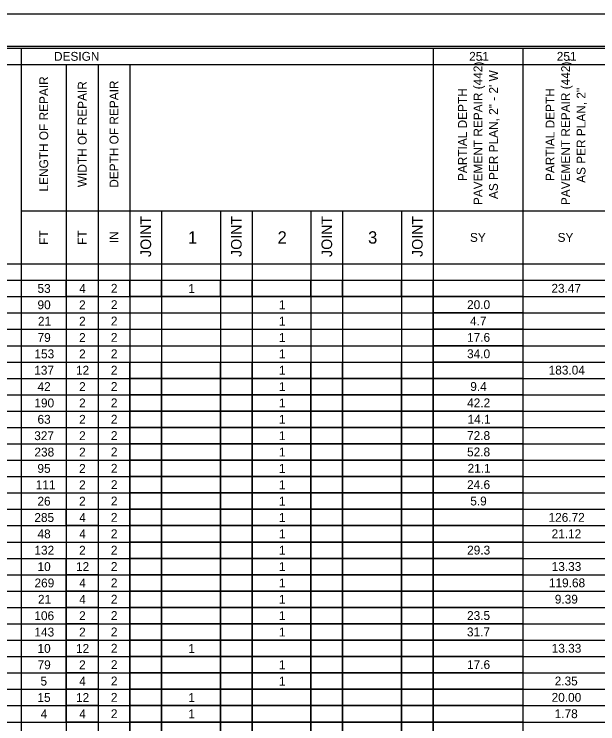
# Model space of a CAD drawing. Extents: x 0 to 34, y 0 to 22.
# Drawn here: x 7.7 to 16.79, y 10.94 to 22 of the extents above; entities that cross this region are included whole.
import ezdxf

# ---------------------------------------------------------------- set-up
doc = ezdxf.new("R2010")
doc.units = 0
for name, color, linetype in [('Default', 7, 'Continuous'), ('SH_Border', 7, 'Continuous'), ('SH_Cut_Line', 7, 'Continuous')]:
    doc.layers.add(name, color=color, linetype=linetype)

msp = doc.modelspace()

# ---------------------------------------------------------------- linework, layer by layer
at = {"layer": 'Default'}
for p, q in [((4.701, 21.469), (28.761, 21.469)), ((7.806, 21.469), (7.806, 1.249)), ((14.226, 21.469), (14.226, 0.844)), ((15.621, 21.469), (15.621, 0.844)), ((4.701, 21.214), (28.761, 21.214)), ((8.511, 21.214), (8.511, 1.249)), ((9.006, 21.214), (9.006, 1.249)), ((9.501, 21.214), (9.501, 1.249)), ((7.806, 18.934), (21.021, 18.934)), ((9.996, 18.934), (9.996, 1.249)), ((10.911, 18.934), (10.911, 1.249)), ((11.406, 18.934), (11.406, 1.249)), ((12.321, 18.934), (12.321, 1.249)), ((12.816, 18.934), (12.816, 1.249)), ((13.731, 18.934), (13.731, 1.249)), ((4.701, 18.109), (28.761, 18.109)), ((4.701, 17.854), (28.761, 17.854)), ((4.701, 17.599), (28.761, 17.599)), ((4.701, 17.344), (28.761, 17.344)), ((4.701, 17.089), (28.761, 17.089)), ((4.701, 16.834), (28.761, 16.834)), ((4.701, 16.579), (28.761, 16.579)), ((4.701, 16.324), (28.761, 16.324)), ((4.701, 16.069), (28.761, 16.069)), ((4.701, 15.814), (28.761, 15.814)), ((4.701, 15.559), (28.761, 15.559)), ((4.701, 15.304), (28.761, 15.304)), ((4.701, 15.049), (28.761, 15.049)), ((4.701, 14.794), (28.761, 14.794)), ((4.701, 14.539), (28.761, 14.539)), ((4.701, 14.284), (28.761, 14.284)), ((4.701, 14.029), (28.761, 14.029)), ((4.701, 13.774), (28.761, 13.774)), ((4.701, 13.519), (28.761, 13.519)), ((4.701, 13.264), (28.761, 13.264)), ((4.701, 13.009), (28.761, 13.009)), ((4.701, 12.754), (28.761, 12.754)), ((4.701, 12.499), (28.761, 12.499)), ((4.701, 12.244), (28.761, 12.244)), ((4.701, 11.989), (28.761, 11.989)), ((4.701, 11.734), (28.761, 11.734)), ((4.701, 11.479), (28.761, 11.479)), ((4.701, 11.224), (28.761, 11.224)), ((4.701, 10.969), (28.761, 10.969))]:
    msp.add_line(p, q, dxfattribs=at)
for points in [[(8.511, 17.854), (9.006, 17.854), (9.006, 17.599), (8.511, 17.599)], [(9.501, 17.854), (9.996, 17.854), (9.996, 17.599), (9.501, 17.599)], [(9.996, 17.854), (10.911, 17.854), (10.911, 17.599), (9.996, 17.599)], [(10.911, 17.854), (11.406, 17.854), (11.406, 17.599), (10.911, 17.599)], [(11.406, 17.854), (12.321, 17.854), (12.321, 17.599), (11.406, 17.599)], [(12.321, 17.854), (12.816, 17.854), (12.816, 17.599), (12.321, 17.599)], [(12.816, 17.854), (13.731, 17.854), (13.731, 17.599), (12.816, 17.599)], [(13.731, 17.854), (14.226, 17.854), (14.226, 17.599), (13.731, 17.599)], [(14.226, 17.854), (15.621, 17.854), (15.621, 17.599), (14.226, 17.599)], [(14.226, 17.599), (15.621, 17.599), (15.621, 17.344), (14.226, 17.344)], [(14.226, 17.344), (15.621, 17.344), (15.621, 17.089), (14.226, 17.089)], [(14.226, 17.089), (15.621, 17.089), (15.621, 16.834), (14.226, 16.834)], [(14.226, 16.834), (15.621, 16.834), (15.621, 16.579), (14.226, 16.579)], [(9.501, 16.579), (9.996, 16.579), (9.996, 16.324), (9.501, 16.324)], [(9.996, 16.579), (10.911, 16.579), (10.911, 16.324), (9.996, 16.324)], [(10.911, 16.579), (11.406, 16.579), (11.406, 16.324), (10.911, 16.324)], [(11.406, 16.579), (12.321, 16.579), (12.321, 16.324), (11.406, 16.324)], [(12.321, 16.579), (12.816, 16.579), (12.816, 16.324), (12.321, 16.324)], [(12.816, 16.579), (13.731, 16.579), (13.731, 16.324), (12.816, 16.324)], [(13.731, 16.579), (14.226, 16.579), (14.226, 16.324), (13.731, 16.324)], [(14.226, 16.579), (15.621, 16.579), (15.621, 16.324), (14.226, 16.324)], [(9.501, 16.324), (9.996, 16.324), (9.996, 16.069), (9.501, 16.069)], [(9.996, 16.324), (10.911, 16.324), (10.911, 16.069), (9.996, 16.069)], [(10.911, 16.324), (11.406, 16.324), (11.406, 16.069), (10.911, 16.069)], [(11.406, 16.324), (12.321, 16.324), (12.321, 16.069), (11.406, 16.069)], [(12.321, 16.324), (12.816, 16.324), (12.816, 16.069), (12.321, 16.069)], [(12.816, 16.324), (13.731, 16.324), (13.731, 16.069), (12.816, 16.069)], [(13.731, 16.324), (14.226, 16.324), (14.226, 16.069), (13.731, 16.069)], [(14.226, 16.324), (15.621, 16.324), (15.621, 16.069), (14.226, 16.069)], [(9.501, 16.069), (9.996, 16.069), (9.996, 15.814), (9.501, 15.814)], [(9.996, 16.069), (10.911, 16.069), (10.911, 15.814), (9.996, 15.814)], [(10.911, 16.069), (11.406, 16.069), (11.406, 15.814), (10.911, 15.814)], [(11.406, 16.069), (12.321, 16.069), (12.321, 15.814), (11.406, 15.814)], [(12.321, 16.069), (12.816, 16.069), (12.816, 15.814), (12.321, 15.814)], [(12.816, 16.069), (13.731, 16.069), (13.731, 15.814), (12.816, 15.814)], [(13.731, 16.069), (14.226, 16.069), (14.226, 15.814), (13.731, 15.814)], [(14.226, 16.069), (15.621, 16.069), (15.621, 15.814), (14.226, 15.814)], [(9.501, 15.814), (9.996, 15.814), (9.996, 15.559), (9.501, 15.559)], [(9.996, 15.814), (10.911, 15.814), (10.911, 15.559), (9.996, 15.559)], [(10.911, 15.814), (11.406, 15.814), (11.406, 15.559), (10.911, 15.559)], [(11.406, 15.814), (12.321, 15.814), (12.321, 15.559), (11.406, 15.559)], [(12.321, 15.814), (12.816, 15.814), (12.816, 15.559), (12.321, 15.559)], [(12.816, 15.814), (13.731, 15.814), (13.731, 15.559), (12.816, 15.559)], [(13.731, 15.814), (14.226, 15.814), (14.226, 15.559), (13.731, 15.559)], [(14.226, 15.814), (15.621, 15.814), (15.621, 15.559), (14.226, 15.559)], [(9.501, 15.559), (9.996, 15.559), (9.996, 15.304), (9.501, 15.304)], [(9.996, 15.559), (10.911, 15.559), (10.911, 15.304), (9.996, 15.304)], [(10.911, 15.559), (11.406, 15.559), (11.406, 15.304), (10.911, 15.304)], [(11.406, 15.559), (12.321, 15.559), (12.321, 15.304), (11.406, 15.304)], [(12.321, 15.559), (12.816, 15.559), (12.816, 15.304), (12.321, 15.304)], [(12.816, 15.559), (13.731, 15.559), (13.731, 15.304), (12.816, 15.304)], [(13.731, 15.559), (14.226, 15.559), (14.226, 15.304), (13.731, 15.304)], [(14.226, 15.559), (15.621, 15.559), (15.621, 15.304), (14.226, 15.304)], [(9.501, 15.304), (9.996, 15.304), (9.996, 15.049), (9.501, 15.049)], [(9.996, 15.304), (10.911, 15.304), (10.911, 15.049), (9.996, 15.049)], [(10.911, 15.304), (11.406, 15.304), (11.406, 15.049), (10.911, 15.049)], [(11.406, 15.304), (12.321, 15.304), (12.321, 15.049), (11.406, 15.049)], [(12.321, 15.304), (12.816, 15.304), (12.816, 15.049), (12.321, 15.049)], [(12.816, 15.304), (13.731, 15.304), (13.731, 15.049), (12.816, 15.049)], [(13.731, 15.304), (14.226, 15.304), (14.226, 15.049), (13.731, 15.049)], [(14.226, 15.304), (15.621, 15.304), (15.621, 15.049), (14.226, 15.049)], [(9.501, 15.049), (9.996, 15.049), (9.996, 14.794), (9.501, 14.794)], [(9.996, 15.049), (10.911, 15.049), (10.911, 14.794), (9.996, 14.794)], [(10.911, 15.049), (11.406, 15.049), (11.406, 14.794), (10.911, 14.794)], [(11.406, 15.049), (12.321, 15.049), (12.321, 14.794), (11.406, 14.794)], [(12.321, 15.049), (12.816, 15.049), (12.816, 14.794), (12.321, 14.794)], [(12.816, 15.049), (13.731, 15.049), (13.731, 14.794), (12.816, 14.794)], [(13.731, 15.049), (14.226, 15.049), (14.226, 14.794), (13.731, 14.794)], [(14.226, 15.049), (15.621, 15.049), (15.621, 14.794), (14.226, 14.794)], [(9.501, 14.794), (9.996, 14.794), (9.996, 14.539), (9.501, 14.539)], [(9.996, 14.794), (10.911, 14.794), (10.911, 14.539), (9.996, 14.539)], [(10.911, 14.794), (11.406, 14.794), (11.406, 14.539), (10.911, 14.539)], [(11.406, 14.794), (12.321, 14.794), (12.321, 14.539), (11.406, 14.539)], [(12.321, 14.794), (12.816, 14.794), (12.816, 14.539), (12.321, 14.539)], [(12.816, 14.794), (13.731, 14.794), (13.731, 14.539), (12.816, 14.539)], [(13.731, 14.794), (14.226, 14.794), (14.226, 14.539), (13.731, 14.539)], [(14.226, 14.794), (15.621, 14.794), (15.621, 14.539), (14.226, 14.539)], [(9.501, 14.539), (9.996, 14.539), (9.996, 14.284), (9.501, 14.284)], [(9.996, 14.539), (10.911, 14.539), (10.911, 14.284), (9.996, 14.284)], [(10.911, 14.539), (11.406, 14.539), (11.406, 14.284), (10.911, 14.284)], [(11.406, 14.539), (12.321, 14.539), (12.321, 14.284), (11.406, 14.284)], [(12.321, 14.539), (12.816, 14.539), (12.816, 14.284), (12.321, 14.284)], [(12.816, 14.539), (13.731, 14.539), (13.731, 14.284), (12.816, 14.284)], [(13.731, 14.539), (14.226, 14.539), (14.226, 14.284), (13.731, 14.284)], [(14.226, 14.539), (15.621, 14.539), (15.621, 14.284), (14.226, 14.284)], [(8.511, 14.284), (9.006, 14.284), (9.006, 14.029), (8.511, 14.029)], [(9.501, 14.284), (9.996, 14.284), (9.996, 14.029), (9.501, 14.029)], [(9.996, 14.284), (10.911, 14.284), (10.911, 14.029), (9.996, 14.029)], [(10.911, 14.284), (11.406, 14.284), (11.406, 14.029), (10.911, 14.029)], [(11.406, 14.284), (12.321, 14.284), (12.321, 14.029), (11.406, 14.029)], [(12.321, 14.284), (12.816, 14.284), (12.816, 14.029), (12.321, 14.029)], [(12.816, 14.284), (13.731, 14.284), (13.731, 14.029), (12.816, 14.029)], [(13.731, 14.284), (14.226, 14.284), (14.226, 14.029), (13.731, 14.029)], [(14.226, 14.284), (15.621, 14.284), (15.621, 14.029), (14.226, 14.029)], [(9.501, 14.029), (9.996, 14.029), (9.996, 13.774), (9.501, 13.774)], [(9.996, 14.029), (10.911, 14.029), (10.911, 13.774), (9.996, 13.774)], [(10.911, 14.029), (11.406, 14.029), (11.406, 13.774), (10.911, 13.774)], [(11.406, 14.029), (12.321, 14.029), (12.321, 13.774), (11.406, 13.774)], [(12.321, 14.029), (12.816, 14.029), (12.816, 13.774), (12.321, 13.774)], [(12.816, 14.029), (13.731, 14.029), (13.731, 13.774), (12.816, 13.774)], [(13.731, 14.029), (14.226, 14.029), (14.226, 13.774), (13.731, 13.774)], [(14.226, 14.029), (15.621, 14.029), (15.621, 13.774), (14.226, 13.774)], [(9.501, 13.774), (9.996, 13.774), (9.996, 13.519), (9.501, 13.519)], [(9.996, 13.774), (10.911, 13.774), (10.911, 13.519), (9.996, 13.519)], [(10.911, 13.774), (11.406, 13.774), (11.406, 13.519), (10.911, 13.519)], [(11.406, 13.774), (12.321, 13.774), (12.321, 13.519), (11.406, 13.519)], [(12.321, 13.774), (12.816, 13.774), (12.816, 13.519), (12.321, 13.519)], [(12.816, 13.774), (13.731, 13.774), (13.731, 13.519), (12.816, 13.519)], [(13.731, 13.774), (14.226, 13.774), (14.226, 13.519), (13.731, 13.519)], [(14.226, 13.774), (15.621, 13.774), (15.621, 13.519), (14.226, 13.519)], [(8.511, 13.519), (9.006, 13.519), (9.006, 13.264), (8.511, 13.264)], [(9.501, 13.519), (9.996, 13.519), (9.996, 13.264), (9.501, 13.264)], [(9.996, 13.519), (10.911, 13.519), (10.911, 13.264), (9.996, 13.264)], [(10.911, 13.519), (11.406, 13.519), (11.406, 13.264), (10.911, 13.264)], [(11.406, 13.519), (12.321, 13.519), (12.321, 13.264), (11.406, 13.264)], [(12.321, 13.519), (12.816, 13.519), (12.816, 13.264), (12.321, 13.264)], [(12.816, 13.519), (13.731, 13.519), (13.731, 13.264), (12.816, 13.264)], [(13.731, 13.519), (14.226, 13.519), (14.226, 13.264), (13.731, 13.264)], [(14.226, 13.519), (15.621, 13.519), (15.621, 13.264), (14.226, 13.264)], [(8.511, 13.264), (9.006, 13.264), (9.006, 13.009), (8.511, 13.009)], [(9.501, 13.264), (9.996, 13.264), (9.996, 13.009), (9.501, 13.009)], [(9.996, 13.264), (10.911, 13.264), (10.911, 13.009), (9.996, 13.009)], [(10.911, 13.264), (11.406, 13.264), (11.406, 13.009), (10.911, 13.009)], [(11.406, 13.264), (12.321, 13.264), (12.321, 13.009), (11.406, 13.009)], [(12.321, 13.264), (12.816, 13.264), (12.816, 13.009), (12.321, 13.009)], [(12.816, 13.264), (13.731, 13.264), (13.731, 13.009), (12.816, 13.009)], [(13.731, 13.264), (14.226, 13.264), (14.226, 13.009), (13.731, 13.009)], [(14.226, 13.264), (15.621, 13.264), (15.621, 13.009), (14.226, 13.009)], [(8.511, 13.009), (9.006, 13.009), (9.006, 12.754), (8.511, 12.754)], [(9.501, 13.009), (9.996, 13.009), (9.996, 12.754), (9.501, 12.754)], [(9.996, 13.009), (10.911, 13.009), (10.911, 12.754), (9.996, 12.754)], [(10.911, 13.009), (11.406, 13.009), (11.406, 12.754), (10.911, 12.754)], [(11.406, 13.009), (12.321, 13.009), (12.321, 12.754), (11.406, 12.754)], [(12.321, 13.009), (12.816, 13.009), (12.816, 12.754), (12.321, 12.754)], [(12.816, 13.009), (13.731, 13.009), (13.731, 12.754), (12.816, 12.754)], [(13.731, 13.009), (14.226, 13.009), (14.226, 12.754), (13.731, 12.754)], [(14.226, 13.009), (15.621, 13.009), (15.621, 12.754), (14.226, 12.754)], [(8.511, 12.754), (9.006, 12.754), (9.006, 12.499), (8.511, 12.499)], [(9.501, 12.754), (9.996, 12.754), (9.996, 12.499), (9.501, 12.499)], [(9.996, 12.754), (10.911, 12.754), (10.911, 12.499), (9.996, 12.499)], [(10.911, 12.754), (11.406, 12.754), (11.406, 12.499), (10.911, 12.499)], [(11.406, 12.754), (12.321, 12.754), (12.321, 12.499), (11.406, 12.499)], [(12.321, 12.754), (12.816, 12.754), (12.816, 12.499), (12.321, 12.499)], [(12.816, 12.754), (13.731, 12.754), (13.731, 12.499), (12.816, 12.499)], [(13.731, 12.754), (14.226, 12.754), (14.226, 12.499), (13.731, 12.499)], [(14.226, 12.754), (15.621, 12.754), (15.621, 12.499), (14.226, 12.499)], [(8.511, 12.499), (9.006, 12.499), (9.006, 12.244), (8.511, 12.244)], [(9.501, 12.499), (9.996, 12.499), (9.996, 12.244), (9.501, 12.244)], [(9.996, 12.499), (10.911, 12.499), (10.911, 12.244), (9.996, 12.244)], [(10.911, 12.499), (11.406, 12.499), (11.406, 12.244), (10.911, 12.244)], [(11.406, 12.499), (12.321, 12.499), (12.321, 12.244), (11.406, 12.244)], [(12.321, 12.499), (12.816, 12.499), (12.816, 12.244), (12.321, 12.244)], [(12.816, 12.499), (13.731, 12.499), (13.731, 12.244), (12.816, 12.244)], [(13.731, 12.499), (14.226, 12.499), (14.226, 12.244), (13.731, 12.244)], [(14.226, 12.499), (15.621, 12.499), (15.621, 12.244), (14.226, 12.244)], [(8.511, 12.244), (9.006, 12.244), (9.006, 11.989), (8.511, 11.989)], [(9.501, 12.244), (9.996, 12.244), (9.996, 11.989), (9.501, 11.989)], [(9.996, 12.244), (10.911, 12.244), (10.911, 11.989), (9.996, 11.989)], [(10.911, 12.244), (11.406, 12.244), (11.406, 11.989), (10.911, 11.989)], [(11.406, 12.244), (12.321, 12.244), (12.321, 11.989), (11.406, 11.989)], [(12.321, 12.244), (12.816, 12.244), (12.816, 11.989), (12.321, 11.989)], [(12.816, 12.244), (13.731, 12.244), (13.731, 11.989), (12.816, 11.989)], [(13.731, 12.244), (14.226, 12.244), (14.226, 11.989), (13.731, 11.989)], [(14.226, 12.244), (15.621, 12.244), (15.621, 11.989), (14.226, 11.989)], [(8.511, 11.989), (9.006, 11.989), (9.006, 11.734), (8.511, 11.734)], [(9.501, 11.989), (9.996, 11.989), (9.996, 11.734), (9.501, 11.734)], [(9.996, 11.989), (10.911, 11.989), (10.911, 11.734), (9.996, 11.734)], [(10.911, 11.989), (11.406, 11.989), (11.406, 11.734), (10.911, 11.734)], [(11.406, 11.989), (12.321, 11.989), (12.321, 11.734), (11.406, 11.734)], [(12.321, 11.989), (12.816, 11.989), (12.816, 11.734), (12.321, 11.734)], [(12.816, 11.989), (13.731, 11.989), (13.731, 11.734), (12.816, 11.734)], [(13.731, 11.989), (14.226, 11.989), (14.226, 11.734), (13.731, 11.734)], [(14.226, 11.989), (15.621, 11.989), (15.621, 11.734), (14.226, 11.734)], [(8.511, 11.734), (9.006, 11.734), (9.006, 11.479), (8.511, 11.479)], [(9.501, 11.734), (9.996, 11.734), (9.996, 11.479), (9.501, 11.479)], [(9.996, 11.734), (10.911, 11.734), (10.911, 11.479), (9.996, 11.479)], [(10.911, 11.734), (11.406, 11.734), (11.406, 11.479), (10.911, 11.479)], [(11.406, 11.734), (12.321, 11.734), (12.321, 11.479), (11.406, 11.479)], [(12.321, 11.734), (12.816, 11.734), (12.816, 11.479), (12.321, 11.479)], [(12.816, 11.734), (13.731, 11.734), (13.731, 11.479), (12.816, 11.479)], [(13.731, 11.734), (14.226, 11.734), (14.226, 11.479), (13.731, 11.479)], [(14.226, 11.734), (15.621, 11.734), (15.621, 11.479), (14.226, 11.479)], [(8.511, 11.479), (9.006, 11.479), (9.006, 11.224), (8.511, 11.224)], [(9.501, 11.479), (9.996, 11.479), (9.996, 11.224), (9.501, 11.224)], [(9.996, 11.479), (10.911, 11.479), (10.911, 11.224), (9.996, 11.224)], [(10.911, 11.479), (11.406, 11.479), (11.406, 11.224), (10.911, 11.224)], [(11.406, 11.479), (12.321, 11.479), (12.321, 11.224), (11.406, 11.224)], [(12.321, 11.479), (12.816, 11.479), (12.816, 11.224), (12.321, 11.224)], [(12.816, 11.479), (13.731, 11.479), (13.731, 11.224), (12.816, 11.224)], [(13.731, 11.479), (14.226, 11.479), (14.226, 11.224), (13.731, 11.224)], [(14.226, 11.479), (15.621, 11.479), (15.621, 11.224), (14.226, 11.224)], [(8.511, 11.224), (9.006, 11.224), (9.006, 10.969), (8.511, 10.969)], [(9.501, 11.224), (9.996, 11.224), (9.996, 10.969), (9.501, 10.969)], [(9.996, 11.224), (10.911, 11.224), (10.911, 10.969), (9.996, 10.969)], [(10.911, 11.224), (11.406, 11.224), (11.406, 10.969), (10.911, 10.969)], [(11.406, 11.224), (12.321, 11.224), (12.321, 10.969), (11.406, 10.969)], [(12.321, 11.224), (12.816, 11.224), (12.816, 10.969), (12.321, 10.969)], [(12.816, 11.224), (13.731, 11.224), (13.731, 10.969), (12.816, 10.969)], [(13.731, 11.224), (14.226, 11.224), (14.226, 10.969), (13.731, 10.969)], [(14.226, 11.224), (15.621, 11.224), (15.621, 10.969), (14.226, 10.969)], [(9.501, 10.969), (9.996, 10.969), (9.996, 10.714), (9.501, 10.714)], [(9.996, 10.969), (10.911, 10.969), (10.911, 10.714), (9.996, 10.714)], [(10.911, 10.969), (11.406, 10.969), (11.406, 10.714), (10.911, 10.714)], [(11.406, 10.969), (12.321, 10.969), (12.321, 10.714), (11.406, 10.714)], [(12.321, 10.969), (12.816, 10.969), (12.816, 10.714), (12.321, 10.714)], [(12.816, 10.969), (13.731, 10.969), (13.731, 10.714), (12.816, 10.714)], [(13.731, 10.969), (14.226, 10.969), (14.226, 10.714), (13.731, 10.714)], [(14.226, 10.969), (15.621, 10.969), (15.621, 10.714), (14.226, 10.714)]]:
    msp.add_lwpolyline(points, close=True, dxfattribs=at)
at = {"layer": 'SH_Border'}
msp.add_lwpolyline([(1.5, 21.5), (33.5, 21.5), (33.5, 0.5), (1.5, 0.5)], close=True, dxfattribs=at)
at = {"layer": 'SH_Cut_Line'}
msp.add_lwpolyline([(0, 0), (34, 0), (34, 22), (0, 22)], close=True, dxfattribs=at)

# ---------------------------------------------------------------- texts
at = {"layer": 'Default'}
for s, height, p in [('DESIGN', 0.138, (8.319, 21.274)), ('251', 0.138, (14.786, 21.274)), ('251', 0.138, (16.151, 21.274)), ('1', 0.193, (10.406, 18.424)), ('2', 0.193, (11.802, 18.424)), ('3', 0.193, (13.212, 18.424)), ('SY', 0.138, (14.799, 18.452)), ('SY', 0.138, (16.164, 18.452)), ('53', 0.138, (8.062, 17.657)), ('4', 0.138, (8.712, 17.657)), ('2', 0.138, (9.205, 17.659)), ('1', 0.138, (10.412, 17.657)), ('23.47', 0.138, (16.068, 17.659)), ('90', 0.138, (8.062, 17.402)), ('2', 0.138, (8.71, 17.402)), ('2', 0.138, (9.205, 17.404)), ('1', 0.138, (11.822, 17.402)), ('20.0', 0.138, (14.754, 17.404)), ('21', 0.138, (8.069, 17.147)), ('2', 0.138, (8.71, 17.147)), ('2', 0.138, (9.205, 17.149)), ('1', 0.138, (11.822, 17.147)), ('4.7', 0.138, (14.8, 17.149)), ('79', 0.138, (8.063, 16.892)), ('2', 0.138, (8.71, 16.892)), ('2', 0.138, (9.205, 16.894)), ('17.6', 0.138, (14.754, 16.894)), ('1', 0.138, (11.822, 16.892)), ('153', 0.138, (8.014, 16.637)), ('2', 0.138, (8.71, 16.637)), ('2', 0.138, (9.205, 16.639)), ('1', 0.138, (11.822, 16.637)), ('34.0', 0.138, (14.754, 16.639)), ('137', 0.138, (8.011, 16.382)), ('12', 0.138, (8.662, 16.382)), ('2', 0.138, (9.205, 16.384)), ('1', 0.138, (11.822, 16.382)), ('183.04', 0.138, (16.025, 16.384)), ('42', 0.138, (8.062, 16.127)), ('2', 0.138, (8.71, 16.127)), ('2', 0.138, (9.205, 16.129)), ('1', 0.138, (11.822, 16.127)), ('9.4', 0.138, (14.804, 16.129)), ('190', 0.138, (8.013, 15.872)), ('2', 0.138, (8.71, 15.872)), ('2', 0.138, (9.205, 15.874)), ('1', 0.138, (11.822, 15.872)), ('42.2', 0.138, (14.755, 15.874)), ('63', 0.138, (8.062, 15.617)), ('2', 0.138, (8.71, 15.617)), ('2', 0.138, (9.205, 15.619)), ('1', 0.138, (11.822, 15.617)), ('14.1', 0.138, (14.762, 15.619)), ('327', 0.138, (8.011, 15.362)), ('2', 0.138, (8.71, 15.362)), ('2', 0.138, (9.205, 15.364)), ('1', 0.138, (11.822, 15.362)), ('72.8', 0.138, (14.754, 15.364)), ('238', 0.138, (8.014, 15.107)), ('2', 0.138, (8.71, 15.107)), ('2', 0.138, (9.205, 15.109)), ('1', 0.138, (11.822, 15.107)), ('52.8', 0.138, (14.754, 15.109)), ('95', 0.138, (8.061, 14.852)), ('2', 0.138, (8.71, 14.852)), ('2', 0.138, (9.205, 14.854)), ('1', 0.138, (11.822, 14.852)), ('21.1', 0.138, (14.762, 14.854)), ('111', 0.138, (8.034, 14.597)), ('2', 0.138, (8.71, 14.597)), ('2', 0.138, (9.205, 14.599)), ('1', 0.138, (11.822, 14.597)), ('24.6', 0.138, (14.754, 14.599)), ('26', 0.138, (8.061, 14.342)), ('2', 0.138, (8.71, 14.342)), ('2', 0.138, (9.205, 14.344)), ('1', 0.138, (11.822, 14.342)), ('5.9', 0.138, (14.804, 14.344)), ('285', 0.138, (8.013, 14.087)), ('4', 0.138, (8.712, 14.087)), ('2', 0.138, (9.205, 14.089)), ('1', 0.138, (11.822, 14.087)), ('126.72', 0.138, (16.023, 14.089)), ('48', 0.138, (8.062, 13.832)), ('4', 0.138, (8.712, 13.832)), ('2', 0.138, (9.205, 13.834)), ('1', 0.138, (11.822, 13.832)), ('21.12', 0.138, (16.071, 13.834)), ('132', 0.138, (8.014, 13.577)), ('2', 0.138, (8.71, 13.577)), ('2', 0.138, (9.205, 13.579)), ('1', 0.138, (11.822, 13.577)), ('29.3', 0.138, (14.755, 13.579)), ('10', 0.138, (8.062, 13.322)), ('12', 0.138, (8.662, 13.322)), ('2', 0.138, (9.205, 13.324)), ('1', 0.138, (11.822, 13.322)), ('13.33', 0.138, (16.072, 13.324)), ('269', 0.138, (8.015, 13.067)), ('4', 0.138, (8.712, 13.067)), ('2', 0.138, (9.205, 13.069)), ('1', 0.138, (11.822, 13.067)), ('119.68', 0.138, (16.029, 13.069)), ('21', 0.138, (8.069, 12.812)), ('4', 0.138, (8.712, 12.812)), ('2', 0.138, (9.205, 12.814)), ('1', 0.138, (11.822, 12.812)), ('9.39', 0.138, (16.121, 12.814)), ('106', 0.138, (8.013, 12.557)), ('2', 0.138, (8.71, 12.557)), ('2', 0.138, (9.205, 12.559)), ('1', 0.138, (11.822, 12.557)), ('23.5', 0.138, (14.754, 12.559)), ('143', 0.138, (8.014, 12.302)), ('2', 0.138, (8.71, 12.302)), ('2', 0.138, (9.205, 12.304)), ('1', 0.138, (11.822, 12.302)), ('31.7', 0.138, (14.752, 12.304)), ('10', 0.138, (8.062, 12.047)), ('12', 0.138, (8.662, 12.047)), ('2', 0.138, (9.205, 12.049)), ('1', 0.138, (10.412, 12.047)), ('13.33', 0.138, (16.072, 12.049)), ('79', 0.138, (8.063, 11.792)), ('2', 0.138, (8.71, 11.792)), ('2', 0.138, (9.205, 11.794)), ('1', 0.138, (11.822, 11.792)), ('17.6', 0.138, (14.754, 11.794)), ('5', 0.138, (8.109, 11.537)), ('4', 0.138, (8.712, 11.537)), ('2', 0.138, (9.205, 11.539)), ('1', 0.138, (11.822, 11.537)), ('2.35', 0.138, (16.119, 11.539)), ('15', 0.138, (8.061, 11.282)), ('12', 0.138, (8.662, 11.282)), ('2', 0.138, (9.205, 11.284)), ('1', 0.138, (10.412, 11.282)), ('20.00', 0.138, (16.071, 11.284)), ('4', 0.138, (8.112, 11.027)), ('4', 0.138, (8.712, 11.027)), ('2', 0.138, (9.205, 11.029)), ('1', 0.138, (10.412, 11.027)), ('1.78', 0.138, (16.119, 11.029))]:
    msp.add_text(s, height=height, dxfattribs=at).set_placement(p)
for s, height, p in [('PAVEMENT REPAIR (442), ', 0.138, (14.993, 19.025)), ('PAVEMENT REPAIR (442), ', 0.138, (16.358, 19.025)), ('AS PER PLAN, 2" - 2\' W', 0.138, (15.234, 19.119)), ('LENGTH OF REPAIR', 0.138, (8.228, 19.237)), ('WIDTH OF REPAIR', 0.138, (8.828, 19.305)), ('DEPTH OF REPAIR', 0.138, (9.323, 19.295)), ('PARTIAL DEPTH ', 0.138, (14.751, 19.4)), ('PARTIAL DEPTH ', 0.138, (16.116, 19.4)), ('AS PER PLAN, 2"', 0.138, (16.599, 19.371)), ('JOINT', 0.1656, (9.832, 18.217)), ('JOINT', 0.1656, (11.242, 18.217)), ('JOINT', 0.1656, (12.652, 18.217)), ('JOINT', 0.1656, (14.062, 18.217)), ('FT', 0.138, (8.228, 18.406)), ('FT', 0.138, (8.828, 18.406)), ('IN', 0.138, (9.323, 18.432))]:
    msp.add_text(s, height=height, rotation=90, dxfattribs=at).set_placement(p)

doc.saveas('drawing.dxf')
